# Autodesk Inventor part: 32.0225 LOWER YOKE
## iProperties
Created: 2012-10
Part Number: 32.0225 LOWER YOKE
Document SubType Name: Modeling
Designer: Administrator
Density: 1.4 g/cm^3
Material: PVC-Piping
Mass: 6.19809 g
Surface Area: 30.7357 cm^2
Volume: 4.42721 cm^3
Author: Administrator
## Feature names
1. Base1
